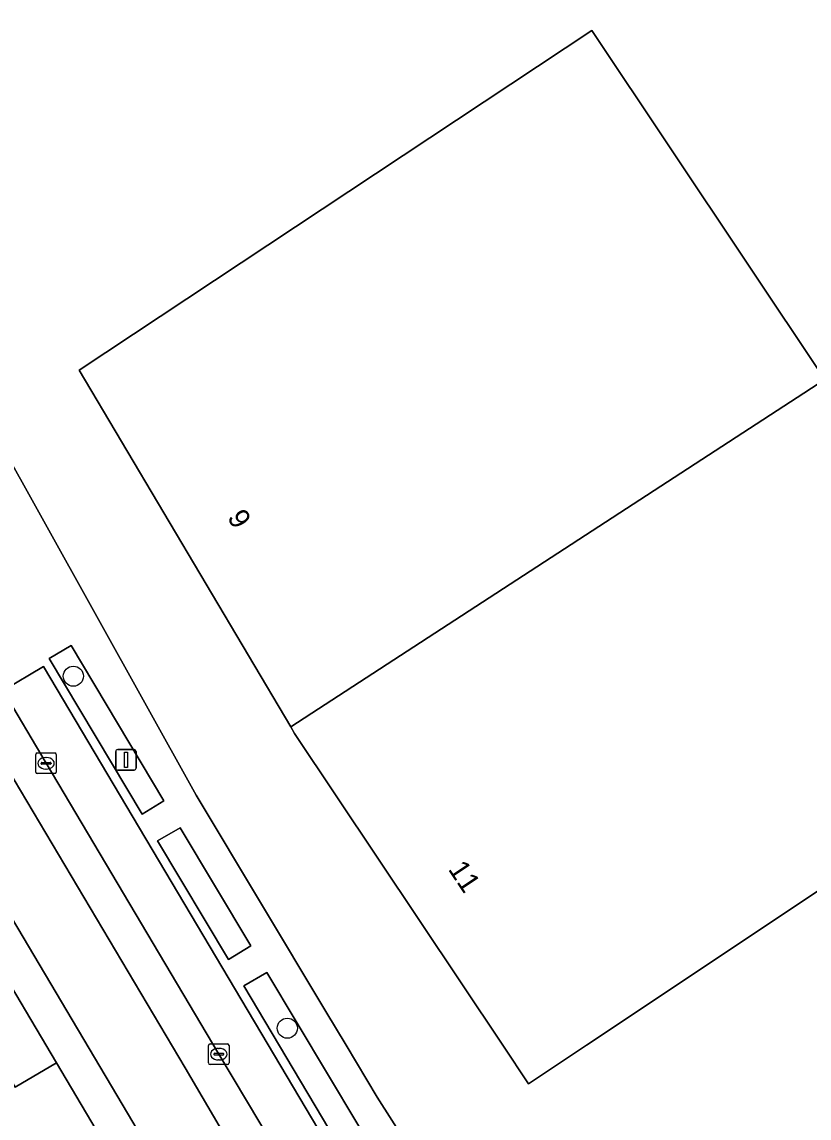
# Model space of a CAD drawing. Extents: x 161771 to 163125, y 382475 to 383179.
# Drawn here: x 162325.4 to 162363.7, y 382896.2 to 382949.5 of the extents above; entities that cross this region are included whole.
import ezdxf

# ---------------------------------------------------------------- set-up
doc = ezdxf.new("R2010")
doc.units = 0
for name, color, linetype in [('IMGEO_Boom', 7, 'Continuous'), ('IMGEO_Erf', 7, 'Continuous'), ('IMGEO_Groenvoorziening', 7, 'Continuous'), ('IMGEO_Kolk', 7, 'Continuous'), ('IMGEO_Lichtmast', 7, 'Continuous'), ('IMGEO_Pand', 7, 'Continuous'), ('IMGEO_Pand_nummerreeks', 7, 'Continuous'), ('IMGEO_Parkeervlak_open', 7, 'Continuous'), ('IMGEO_Rijbaan_lokaal_gesloten', 7, 'Continuous'), ('IMGEO_Voetpad_open', 7, 'Continuous')]:
    doc.layers.add(name, color=color, linetype=linetype)

msp = doc.modelspace()

# ---------------------------------------------------------------- linework, layer by layer
at = {"layer": 'IMGEO_Boom'}
for centre in [(162327.931, 382917.648), (162338.332, 382900.53)]:
    msp.add_circle(centre, 0.489, dxfattribs=at)
at = {"layer": 'IMGEO_Erf'}
msp.add_lwpolyline([(162282.694, 382998.745), (162285.645, 382993.994), (162299.205, 382971.267), (162304.602, 382962.221), (162323.715, 382930.187), (162324.058, 382929.531), (162333.904, 382911.866), (162340.209, 382901.345), (162341.191, 382899.707), (162342.707, 382897.177), (162347.841, 382889.118), (162350.419, 382884.987), (162352.762, 382884.507), (162396.81, 382874.496)], dxfattribs=at)
msp.add_lwpolyline([(162352.869, 382899.707), (162350.053, 382897.83), (162348.801, 382899.707), (162338.688, 382914.864), (162338.501, 382915.18), (162328.219, 382932.526), (162353.132, 382949.043), (162364.461, 382932.073), (162377.173, 382940.548), (162388.545, 382923.491), (162376.122, 382915.209)], close=True, dxfattribs=at)
at = {"layer": 'IMGEO_Groenvoorziening'}
for points in [[(162332.327, 382911.586), (162327.83, 382919.136), (162326.759, 382918.517), (162331.274, 382910.938)], [(162336.56, 382904.535), (162333.122, 382910.269), (162332.026, 382909.647), (162335.468, 382903.877)], [(162337.338, 382903.237), (162336.212, 382902.585), (162342.088, 382892.713), (162343.227, 382893.391)]]:
    msp.add_lwpolyline(points, close=True, dxfattribs=at)
at = {"layer": 'IMGEO_Kolk'}
for p, q in [((162326.102, 382912.988), (162326.102, 382913.84)), ((162326.177, 382913.914), (162327.029, 382913.914)), ((162327.103, 382913.84), (162327.103, 382912.988)), ((162326.361, 382913.408), (162326.361, 382913.42)), ((162326.799, 382913.371), (162326.401, 382913.371)), ((162326.404, 382913.457), (162326.802, 382913.457)), ((162326.59, 382913.694), (162326.615, 382913.694)), ((162326.845, 382913.42), (162326.845, 382913.408)), ((162327.029, 382912.914), (162326.177, 382912.914)), ((162326.613, 382913.134), (162326.588, 382913.134)), ((162334.501, 382898.84), (162334.501, 382899.692)), ((162334.576, 382899.766), (162335.428, 382899.766)), ((162334.989, 382899.546), (162335.014, 382899.546)), ((162335.502, 382899.692), (162335.502, 382898.84)), ((162334.76, 382899.26), (162334.76, 382899.272)), ((162335.198, 382899.223), (162334.8, 382899.223)), ((162334.803, 382899.309), (162335.201, 382899.309)), ((162335.012, 382898.986), (162334.987, 382898.986)), ((162335.244, 382899.272), (162335.244, 382899.26)), ((162335.428, 382898.766), (162334.576, 382898.766))]:
    msp.add_line(p, q, dxfattribs=at)
for points in [[(162326.102, 382912.988), (162326.102, 382913.84)], [(162326.177, 382913.914), (162327.029, 382913.914)], [(162327.103, 382913.84), (162327.103, 382912.988)], [(162327.029, 382912.914), (162326.177, 382912.914)], [(162334.501, 382898.84), (162334.501, 382899.692)], [(162334.576, 382899.766), (162335.428, 382899.766)], [(162335.502, 382899.692), (162335.502, 382898.84)], [(162335.428, 382898.766), (162334.576, 382898.766)]]:
    msp.add_lwpolyline(points, dxfattribs=at)
for centre, radius, start, end in [((162326.179, 382913.838), 0.0765, 91.552, 178.448), ((162326.179, 382913.838), 0.0765, 91.552, 178.448), ((162327.027, 382913.838), 0.0765, 1.552, 88.448), ((162327.027, 382913.838), 0.0765, 1.552, 88.448), ((162326.401, 382913.417), 0.0403, 85.8775, 175.7526), ((162326.398, 382913.407), 0.0366, 178.938, 274.7102), ((162326.802, 382913.414), 0.043, 264.8664, 352.4533), ((162326.806, 382913.419), 0.0386, 1.7309, 96.639), ((162326.179, 382912.99), 0.0765, 181.552, 268.448), ((162326.179, 382912.99), 0.0765, 181.552, 268.448), ((162327.027, 382912.99), 0.0765, 271.552, 358.448), ((162327.027, 382912.99), 0.0765, 271.552, 358.448), ((162334.578, 382899.69), 0.0765, 91.552, 178.448), ((162334.578, 382899.69), 0.0765, 91.552, 178.448), ((162335.426, 382899.69), 0.0765, 1.552, 88.448), ((162335.426, 382899.69), 0.0765, 1.552, 88.448), ((162334.8, 382899.269), 0.0403, 85.8775, 175.7526), ((162334.797, 382899.259), 0.0366, 178.938, 274.7102), ((162335.201, 382899.266), 0.043, 264.8664, 352.4533), ((162335.205, 382899.271), 0.0386, 1.7309, 96.639), ((162334.578, 382898.842), 0.0765, 181.552, 268.448), ((162334.578, 382898.842), 0.0765, 181.552, 268.448), ((162335.426, 382898.842), 0.0765, 271.552, 358.448), ((162335.426, 382898.842), 0.0765, 271.552, 358.448)]:
    msp.add_arc(centre, radius, start, end, dxfattribs=at)
for centre, major_axis, ratio, start_param, end_param in [((162326.589, 382913.414), (-0.387, 0.002), 0.722429, 4.712389, 7.853982), ((162326.614, 382913.414), (-0.39, 0.002), 0.717154, 1.570796, 4.712389), ((162334.988, 382899.266), (-0.387, 0.002), 0.722429, 4.712389, 7.853982), ((162335.013, 382899.266), (-0.39, 0.002), 0.717154, 1.570796, 4.712389)]:
    msp.add_ellipse(centre, major_axis=major_axis, ratio=ratio, start_param=start_param, end_param=end_param, dxfattribs=at)
at = {"layer": 'IMGEO_Lichtmast'}
for p, q in [((162329.991, 382913.181), (162329.991, 382913.981)), ((162329.991, 382913.981), (162329.991, 382913.181)), ((162330.091, 382914.081), (162330.881, 382914.081)), ((162330.881, 382914.081), (162330.091, 382914.081)), ((162330.981, 382913.981), (162330.981, 382913.181)), ((162330.981, 382913.181), (162330.981, 382913.981)), ((162330.881, 382913.081), (162330.091, 382913.081)), ((162330.091, 382913.081), (162330.881, 382913.081))]:
    msp.add_line(p, q, dxfattribs=at)
msp.add_lwpolyline([(162330.411, 382913.956), (162330.561, 382913.956), (162330.561, 382913.206), (162330.411, 382913.206), (162330.411, 382913.956)], dxfattribs=at)
for centre, start, end in [((162330.091, 382913.981), 90, 180), ((162330.091, 382913.981), 90, 180), ((162330.881, 382913.981), 0, 90), ((162330.881, 382913.981), 360, 90), ((162330.091, 382913.181), 180, 270), ((162330.091, 382913.181), 180, 270), ((162330.881, 382913.181), 270, 0), ((162330.881, 382913.181), 270, 0)]:
    msp.add_arc(centre, 0.1, start, end, dxfattribs=at)
at = {"layer": 'IMGEO_Pand'}
for points in [[(162364.461, 382932.073), (162353.132, 382949.043), (162328.219, 382932.526), (162338.501, 382915.18)], [(162364.461, 382932.073), (162338.501, 382915.18), (162338.688, 382914.864), (162348.801, 382899.707), (162350.053, 382897.83), (162352.869, 382899.707), (162376.122, 382915.209), (162388.545, 382923.491), (162377.173, 382940.548)]]:
    msp.add_lwpolyline(points, close=True, dxfattribs=at)
at = {"layer": 'IMGEO_Parkeervlak_open'}
for points in [[(162324.516, 382916.948), (162326.603, 382913.414), (162335.002, 382899.266), (162339.727, 382891.336), (162341.708, 382892.457), (162326.472, 382918.127)], [(162320.653, 382909.74), (162317.99, 382914.237), (162317.13, 382913.727), (162316.009, 382913.063), (162325.106, 382897.667), (162327.107, 382898.845)]]:
    msp.add_lwpolyline(points, close=True, dxfattribs=at)
at = {"layer": 'IMGEO_Rijbaan_lokaal_gesloten'}
for points in [[(162252.687, 383027.32), (162258.27, 383017.942), (162277.114, 382986.385), (162314.204, 382923.986), (162330.304, 382896.843), (162338.934, 382882.25), (162339.793, 382880.803)], [(162341.807, 382884.166), (162340.693, 382886.098), (162333.368, 382898.598), (162322.883, 382916.238), (162309.554, 382938.696), (162306.687, 382943.516), (162275.079, 382996.8)], [(162275.079, 382996.8), (162306.687, 382943.516), (162309.554, 382938.696), (162322.883, 382916.238), (162333.368, 382898.598), (162340.693, 382886.098), (162341.807, 382884.166)], [(162344.002, 382884.116), (162343.193, 382885.422), (162339.727, 382891.336), (162335.002, 382899.266), (162326.603, 382913.414), (162324.516, 382916.948), (162318.235, 382927.528), (162317.64, 382928.532), (162316.912, 382929.741), (162308.432, 382943.993), (162300.77, 382956.887), (162300.224, 382957.807), (162293.232, 382969.581), (162288.514, 382977.525), (162281.441, 382989.446), (162278.279, 382994.741), (162277.713, 382995.702)], [(162339.793, 382880.803), (162338.934, 382882.25), (162330.304, 382896.843), (162314.204, 382923.986), (162277.114, 382986.385)], [(162295.546, 382952.022), (162297.385, 382948.927), (162297.447, 382948.823), (162302.486, 382940.342), (162311.925, 382924.471), (162312.752, 382923.086), (162312.819, 382922.973), (162314.64, 382919.896), (162317.99, 382914.237), (162320.653, 382909.74), (162327.107, 382898.845), (162329.048, 382895.587), (162330.45, 382893.21), (162336.215, 382883.528), (162338.393, 382879.852)]]:
    msp.add_lwpolyline(points, dxfattribs=at)
at = {"layer": 'IMGEO_Voetpad_open'}
for points in [[(162298.198, 382970.688), (162299.205, 382971.267), (162285.645, 382993.994), (162282.694, 382998.745), (162282.561, 382998.663), (162282.621, 382998.564), (162281.332, 382997.822), (162277.713, 382995.702), (162278.279, 382994.741), (162281.441, 382989.446), (162283.412, 382990.65), (162295.219, 382970.753), (162293.232, 382969.581), (162300.224, 382957.807), (162302.215, 382959.014), (162320.137, 382928.801), (162318.235, 382927.528), (162324.516, 382916.948), (162326.472, 382918.127), (162341.708, 382892.457), (162339.727, 382891.336), (162343.193, 382885.422), (162344.002, 382884.116)], [(162350.419, 382884.987), (162347.841, 382889.118), (162342.707, 382897.177), (162341.191, 382899.707), (162340.209, 382901.345), (162333.904, 382911.866), (162324.058, 382929.531), (162323.715, 382930.187), (162304.602, 382962.221), (162303.031, 382961.271)], [(162329.048, 382895.587), (162327.107, 382898.845), (162325.106, 382897.667), (162316.009, 382913.063), (162317.13, 382913.727), (162313.784, 382919.38), (162312.27, 382918.468), (162310.158, 382917.241), (162304.516, 382926.628), (162306.675, 382927.91), (162310.448, 382921.543), (162312.819, 382922.973), (162312.752, 382923.086), (162311.9, 382922.562), (162310.788, 382921.877), (162295.457, 382947.642)]]:
    msp.add_lwpolyline(points, dxfattribs=at)
for points in [[(162331.274, 382910.938), (162326.759, 382918.517), (162327.83, 382919.136), (162332.327, 382911.586)], [(162335.468, 382903.877), (162332.026, 382909.647), (162333.122, 382910.269), (162336.56, 382904.535)], [(162336.212, 382902.585), (162337.338, 382903.237), (162343.227, 382893.391), (162342.088, 382892.713)]]:
    msp.add_lwpolyline(points, close=True, dxfattribs=at)

# ---------------------------------------------------------------- texts
at = {"layer": 'IMGEO_Pand_nummerreeks'}
for s, rotation, p in [('9', 300.657, (162335.388, 382925.375)), ('11', 303.711, (162346.122, 382908.263))]:
    msp.add_text(s, height=1, rotation=rotation, dxfattribs=at).set_placement(p)

doc.saveas('drawing.dxf')
